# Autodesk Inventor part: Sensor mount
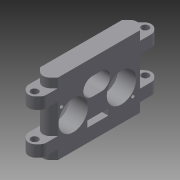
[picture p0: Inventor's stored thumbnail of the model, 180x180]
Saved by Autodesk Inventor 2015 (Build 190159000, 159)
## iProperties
Created: 2014-10
Part Number: Sensor mount
Material: Generic
Document SubType Name: Modeling
Designer: carlos
Density: 1 g/cm^3
Appearance: Default
Author: carlos
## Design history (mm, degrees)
sketch "Sketch5"
  geometry: L1 (22.285, 27.535)-(-17.715, 27.535); L2 (-17.715, 27.535)-(-17.715, -42.465); L3 (-17.715, -42.465)-(22.285, -42.465); L4 (22.285, -42.465)-(22.285, 27.535); L5 (9.714, -29.108)-(-10.286, -29.108); L6 (-10.286, -29.108)-(-10.286, 15.892); L7 (-10.286, 15.892)-(9.714, 15.892); L8 (9.714, 15.892)-(9.714, -29.108); L9 (8.371, -13.765)-(8.371, 1.235); L10 (13.371, -8.765)-(13.371, -3.765); L11 (3.371, -3.765)-(3.371, -8.765); L12 (-6.786, -12.722)-(-10.286, -12.722); L13 (-10.286, -12.722)-(-10.286, -1.039); L14 (-10.286, -1.039)-(-6.786, -1.039); L15 (-6.786, -1.039)-(-6.786, -12.722); C1 r 8.25 at (-0.286, -20.108); C2 r 8.25 at (-0.286, 6.892); C3 r 1 at (7.214, 13.392); C4 r 1 at (-7.786, -26.608); A1 r 5 centre (8.371, -8.765) between (3.371, -8.765) and (13.371, -8.765); A2 r 5 centre (8.371, -3.765) between (13.371, -3.765) and (3.371, -3.765); 2 further points
  constraints: 32 end point, 7 parallel, 6 centre point, 6 point on circle, 4 tangent, 3 horizontal, 3 perpendicular, 3 point on line, 1 midpoint, 1 vertical
  dimensions: "d13" = 20 distance of L6.end L7.end; "d14" = 45 distance of L5.end L6.end; "d15" = 27 distance of C1.centre C2.centre; "d16" = 10 distance from line of L8 C2.centre; "d17" = 10 distance from line of L6 C2.centre (derived); "d18" = 16.5 diameter of C2; "d19" = 16.5 diameter of C1; "d20" = 9 distance from line of L7 C2.centre; "d21" = 9 distance from line of L5 C1.centre; "d22" = 2 diameter of C3; "d23" = 2 diameter of C4; "d24" = 15 horizontal distance of C4.centre C3.centre; "d25" = 40 vertical distance of C3.centre C4.centre; "d26" = 2.5 distance from line of L7 C3.centre; "d27" = 2.5 distance from line of L5 C4.centre (derived); "d28" = 2.5 distance from line of L8 C3.centre; "d29" = 2.5 distance from line of L6 C4.centre (derived); "d32" = 40 distance of L1.start L1.end; "d33" = 70 distance of L1.end L2.end; "d91" = 10 distance between parallel lines of L11 L10; "d93" = 5 distance of A2.centre A1.centre
extrude "Extrusion3" new body sketch "Sketch5" distance "d30" = 10; taper "d31" = 0 deg
sketch "Sketch6"
  geometry: L1 (-42.465, -17.715)-(-42.465, 22.285) reference; L2 (-42.465, 10.635)-(-34.465, 10.635); L3 (-34.465, 10.635)-(-34.465, -6.065); L4 (-34.465, -6.065)-(-42.465, -6.065); L5 (-42.465, -6.065)-(-42.465, 10.635); L6 (27.535, 22.285)-(27.535, -17.715) reference; L7 (27.535, 10.635)-(19.535, 10.635); L8 (19.535, 10.635)-(19.535, -6.065); L9 (19.535, -6.065)-(27.535, -6.065); L10 (27.535, -6.065)-(27.535, 10.635); L11 (-42.465, 22.285)-(-34.465, 22.285); L12 (-34.465, 22.285)-(-34.465, 17.135); L13 (-34.465, 17.135)-(-42.465, 17.135); L14 (-42.465, 17.135)-(-42.465, 22.285); L15 (27.535, 22.285)-(19.535, 22.285); L16 (19.535, 22.285)-(19.535, 17.135); L17 (19.535, 17.135)-(27.535, 17.135); L18 (27.535, 17.135)-(27.535, 22.285); L19 (27.535, -17.715)-(19.535, -17.715); L20 (19.535, -17.715)-(19.535, -12.565); L21 (19.535, -12.565)-(27.535, -12.565); L22 (27.535, -12.565)-(27.535, -17.715); L23 (-42.465, -17.715)-(-34.465, -17.715); L24 (-34.465, -17.715)-(-34.465, -12.565); L25 (-34.465, -12.565)-(-42.465, -12.565); L26 (-42.465, -12.565)-(-42.465, -17.715); 1 further point
  constraints: 48 end point, 12 parallel, 8 point on line, 6 horizontal, 6 perpendicular
  dimensions: "d34" = 6.5 distance between parallel lines of L7 L17; "d35" = 6.5 distance between parallel lines of L21 L9; "d36" = 6.5 distance between parallel lines of L2 L13 (derived); "d37" = 6.5 distance between parallel lines of L25 L4 (derived); "d38" = 8 distance between parallel lines of L6 L16; "d39" = 8 distance between parallel lines of L12 L1; "d40" = 8 distance between parallel lines of L8 L10; "d41" = 8 distance between parallel lines of L3 L1; "d57" = 5.15 distance between parallel lines of L15 L17; "d58" = 5.15 distance between parallel lines of L19 L21; "d65" = 16.7 distance between parallel lines of L7 L9 (derived); "d66" = 11.65 distance between parallel lines of L15 L7 (derived); "d67" = 28.35 distance between parallel lines of L9 L15 (derived)
extrude "Extrusion4" cut sketch "Sketch6" stored distance "d42" = 4; taper "d43" = 0 deg
sketch "Sketch7"
  geometry: L1 (0, 8)-(10, 8) reference; L2 (10, 8)-(10, 0) reference; L3 (10, -54)-(10, -62) reference; L4 (10, -62)-(0, -62) reference; C1 r 1.5 at (5, 4); C2 r 1.5 at (5, -58); 1 further point
  constraints: 2 centre point
  dimensions: "d44" = 4 distance from line of L1 C1.centre; "d45" = 5 distance from line of L2 C1.centre; "d46" = 5 distance from line of L3 C2.centre; "d47" = 4 distance from line of L4 C2.centre; "d48" = 3 diameter of C2; "d49" = 3 diameter of C1
hole "Hole2" sketch "Sketch7" at (5, 4), (5, -58) diameter "d50" = 4; stored, may be unused: countersink angle "d54" = 82 deg, drill point angle "d56" = 118 deg; dims "d51" = 19.05, "d52" = 9.525, "d53" = 6.35, "d55" = 25.4
extrude "Extrusion5" cut sketch "Sketch5" stored distance "d59" = 4; taper "d60" = 0 deg
fillet "Fillet4" dims "d64" = 0.1
sketch "Sketch8"
  geometry: 1 further point
chamfer "Chamfer3" distance "d82" = 4; stored, may be unused: second distance "d83" = 2, angle "d84" = 45 deg
chamfer "Chamfer4" distance "d86" = 4; stored, may be unused: second distance "d87" = 2, angle "d88" = 45 deg
fillet "Fillet14" dims "d89" = 4
fillet "Fillet15" dims "d90" = 4
body "Solid2"
